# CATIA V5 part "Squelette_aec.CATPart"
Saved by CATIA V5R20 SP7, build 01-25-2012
Part number: Squelette_aec
Publications: "Plan.2", "Droite.8", "Droite.9", "Droite.10"
Bounding box of the stored display mesh (mm): x 0 to 20, y 0 to 34.202, z 0 to 93.969
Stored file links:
  G:\bon\Nouveau dossier\Squelette_aec.CATPart
  C:\Documents and Settings\cgirerd\Bureau\Copie de Copie de Nouveau dossier\765.CATProduct
  G:\bon\Nouveau dossier\mecanism.skl.CATProduct
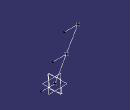
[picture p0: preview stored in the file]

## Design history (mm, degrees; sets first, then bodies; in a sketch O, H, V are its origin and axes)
Set1
  Point1 "A": linked copy from another document
  Point2 "E": linked copy from another document
  Point3 "C": linked copy from another document
  Plane1: linked copy from another document
Set2
  Line1: type PtPt, FirstPoint Point1, SecondPoint Point2
  Line2: type PtPt, FirstPoint Point2, SecondPoint Point3
  Line3: type Normal, RefPoint Point1, RefSkin Plane1, Start 0, End 20
  Line4: type Normal, RefPoint Point2, RefSkin Plane1, Start 0, End 20
  Line5: type Normal, RefPoint Point3, RefSkin Plane1, Start 0, End 20
Body1 (main body)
